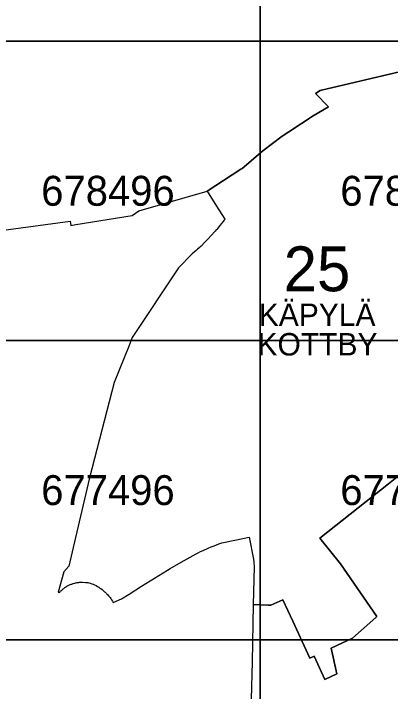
# Model space of a CAD drawing. Extents: x 25485000 to 25520000, y 6656775 to 6690000.
# Drawn here: x 25496176 to 25497436, y 6676827 to 6679092 of the extents above; entities that cross this region are included whole.
import ezdxf

# ---------------------------------------------------------------- set-up
doc = ezdxf.new("R2010")
doc.units = 0
doc.layers.add('Level 63', color=7, linetype='Continuous')

msp = doc.modelspace()

# ---------------------------------------------------------------- linework, layer by layer
at = {"layer": 'Level 63'}
for points in [[(25496000, 6679000), (25497000, 6679000), (25497000, 6680000), (25496000, 6680000)], [(25497000, 6679000), (25498000, 6679000), (25498000, 6680000), (25497000, 6680000)], [(25496000, 6678000), (25497000, 6678000), (25497000, 6679000), (25496000, 6679000)], [(25497000, 6678000), (25498000, 6678000), (25498000, 6679000), (25497000, 6679000)], [(25496000, 6677000), (25497000, 6677000), (25497000, 6678000), (25496000, 6678000)], [(25497000, 6677000), (25498000, 6677000), (25498000, 6678000), (25497000, 6678000)], [(25496000, 6676000), (25497000, 6676000), (25497000, 6677000), (25496000, 6677000)], [(25497000, 6676000), (25498000, 6676000), (25498000, 6677000), (25497000, 6677000)]]:
    msp.add_lwpolyline(points, close=True, dxfattribs=at)
for points in [[(25495688, 6678307.4), (25496365.4, 6678399), (25496367.4, 6678384.1), (25496384.4, 6678386.9), (25496572.1, 6678417.8), (25496594.5, 6678432.7), (25496823.4, 6678498.8), (25496936.3, 6678571.8), (25496939.8, 6678574.8), (25497009.6, 6678633.8), (25497074.2, 6678682.5), (25497096, 6678696.7), (25497178, 6678750.3), (25497228.6, 6678780), (25497185.7, 6678824.9), (25497201, 6678835), (25497812.2, 6678979.1)], [(25497812.2, 6678979.1), (25497201, 6678835), (25497185.7, 6678824.9), (25497228.6, 6678780), (25497178, 6678750.3), (25497096, 6678696.7), (25497074.2, 6678682.5), (25497009.6, 6678633.8), (25496939.8, 6678574.8), (25496936.3, 6678571.8), (25496823.4, 6678498.8), (25496854.6, 6678448.8), (25496882, 6678404.7), (25496880.8, 6678403.2), (25496879.9, 6678402), (25496874.6, 6678395.1), (25496870.8, 6678390.2), (25496865.9, 6678384), (25496861.3, 6678378.4), (25496858.5, 6678374.9), (25496855.1, 6678370.8), (25496854.4, 6678370.1), (25496853.9, 6678369.5), (25496849.8, 6678364.7), (25496837.2, 6678350.6), (25496826.9, 6678339.5), (25496814.8, 6678327.2), (25496802.8, 6678315.5), (25496795, 6678308.2), (25496791.1, 6678304.6), (25496786.6, 6678300.6), (25496773.6, 6678289.2), (25496727.3, 6678242.3), (25496572.5, 6678009.5), (25496562, 6677983.4), (25496512.2, 6677859.6), (25496429.9, 6677540.7), (25496383.2, 6677341.6), (25496360.8, 6677245.7), (25496343.8, 6677226.6), (25496325.2, 6677158.8), (25496329.3, 6677157.8), (25496331.7, 6677160.5), (25496333.1, 6677161.9), (25496334.6, 6677163.4), (25496337.1, 6677165.8), (25496339.2, 6677167.8), (25496341.5, 6677169.7), (25496343.7, 6677171.5), (25496344.9, 6677172.4), (25496346.3, 6677173.5), (25496347.5, 6677174.3), (25496351.7, 6677177.1), (25496354.6, 6677178.8), (25496356.3, 6677179.9), (25496359.1, 6677181.3), (25496361.1, 6677182.3), (25496363.3, 6677183.4), (25496365.7, 6677184.5), (25496368.6, 6677185.7), (25496370.4, 6677186.3), (25496373.2, 6677187.3), (25496375.5, 6677188.1), (25496380.6, 6677189.5), (25496383.2, 6677190.1), (25496385.7, 6677190.7), (25496388.5, 6677191.2), (25496390.3, 6677191.5), (25496393.7, 6677191.9), (25496396.1, 6677192.1), (25496406.5, 6677192.5), (25496417, 6677191.9), (25496420.8, 6677191.3), (25496424, 6677190.8), (25496427.3, 6677190.1), (25496432.6, 6677188.7), (25496437.3, 6677187.2), (25496442.6, 6677185.3), (25496447.1, 6677183.3), (25496452.1, 6677180.8), (25496456.3, 6677178.4), (25496461.3, 6677175.3), (25496463.4, 6677173.8), (25496465, 6677172.6), (25496467.6, 6677170.8), (25496472, 6677167.5), (25496475.8, 6677164.4), (25496477, 6677163.4), (25496480.1, 6677160.7), (25496481.9, 6677159.1), (25496483.3, 6677157.8), (25496484.5, 6677156.6), (25496485.2, 6677155.9), (25496487, 6677154.1), (25496488.4, 6677152.6), (25496489.6, 6677151.3), (25496489.8, 6677151.2), (25496489.8, 6677151.1), (25496489.9, 6677151), (25496490.1, 6677150.8), (25496490.4, 6677150.4), (25496491, 6677149.9), (25496493.9, 6677146.6), (25496496.4, 6677143.6), (25496498.5, 6677140.9), (25496500.9, 6677137.7), (25496502.1, 6677136), (25496503.7, 6677133.7), (25496506.5, 6677129.4), (25496509.5, 6677124.6), (25496537.2, 6677137), (25496562.1, 6677152.5), (25496604.1, 6677178.7), (25496690.7, 6677232.6), (25496699.2, 6677237.9), (25496736.8, 6677259.1), (25496776.2, 6677281.3), (25496786.8, 6677287.2), (25496792.9, 6677290.3), (25496801.4, 6677294.5), (25496809.6, 6677298.4), (25496826.3, 6677305.9), (25496837, 6677310.4), (25496847, 6677314.4), (25496862.3, 6677320.1), (25496872, 6677323.4), (25496883.8, 6677325.9), (25496942.4, 6677338.5), (25496963.3, 6677343), (25496978.2, 6677269.7), (25496979.7, 6677259.1), (25496980.5, 6677243.8), (25496977.6, 6677117.4), (25497027.6, 6677116), (25497035.9, 6677115.7), (25497076, 6677133.9), (25497109.7, 6677061.7), (25497167, 6676939.1), (25497180.6, 6676945.5), (25497217, 6676867.5), (25497257.3, 6676886.4), (25497237.6, 6676972.1), (25497308.8, 6677005.4), (25497386.8, 6677074.3), (25497390.4, 6677077.4), (25497268.9, 6677253.4), (25497200.3, 6677339.8), (25497429.3, 6677520.9), (25497468.6, 6677551.9)], [(25495688, 6678307.4), (25496365.4, 6678399), (25496367.4, 6678384.1), (25496384.4, 6678386.9), (25496572.1, 6678417.8), (25496594.5, 6678432.7), (25496823.4, 6678498.8), (25496854.6, 6678448.8), (25496882, 6678404.7), (25496880.8, 6678403.2), (25496879.9, 6678402), (25496874.6, 6678395.1), (25496870.8, 6678390.2), (25496865.9, 6678384), (25496861.3, 6678378.4), (25496858.5, 6678374.9), (25496855.1, 6678370.8), (25496854.4, 6678370.1), (25496853.9, 6678369.5), (25496849.8, 6678364.7), (25496837.2, 6678350.6), (25496826.9, 6678339.5), (25496814.8, 6678327.2), (25496802.8, 6678315.5), (25496795, 6678308.2), (25496791.1, 6678304.6), (25496786.6, 6678300.6), (25496773.6, 6678289.2), (25496727.3, 6678242.3), (25496572.5, 6678009.5), (25496562, 6677983.4), (25496512.2, 6677859.6), (25496429.9, 6677540.7), (25496383.2, 6677341.6), (25496360.8, 6677245.7), (25496343.8, 6677226.6), (25496325.2, 6677158.8), (25496329.3, 6677157.8), (25496331.7, 6677160.5), (25496333.1, 6677161.9), (25496334.6, 6677163.4), (25496337.1, 6677165.8), (25496339.2, 6677167.8), (25496341.5, 6677169.7), (25496343.7, 6677171.5), (25496344.9, 6677172.4), (25496346.3, 6677173.5), (25496347.5, 6677174.3), (25496351.7, 6677177.1), (25496354.6, 6677178.8), (25496356.3, 6677179.9), (25496359.1, 6677181.3), (25496361.1, 6677182.3), (25496363.3, 6677183.4), (25496365.7, 6677184.5), (25496368.6, 6677185.7), (25496370.4, 6677186.3), (25496373.2, 6677187.3), (25496375.5, 6677188.1), (25496380.6, 6677189.5), (25496383.2, 6677190.1), (25496385.7, 6677190.7), (25496388.5, 6677191.2), (25496390.3, 6677191.5), (25496393.7, 6677191.9), (25496396.1, 6677192.1), (25496406.5, 6677192.5), (25496417, 6677191.9), (25496420.8, 6677191.3), (25496424, 6677190.8), (25496427.3, 6677190.1), (25496432.6, 6677188.7), (25496437.3, 6677187.2), (25496442.6, 6677185.3), (25496447.1, 6677183.3), (25496452.1, 6677180.8), (25496456.3, 6677178.4), (25496461.3, 6677175.3), (25496463.4, 6677173.8), (25496465, 6677172.6), (25496467.6, 6677170.8), (25496472, 6677167.5), (25496475.8, 6677164.4), (25496477, 6677163.4), (25496480.1, 6677160.7), (25496481.9, 6677159.1), (25496483.3, 6677157.8), (25496484.5, 6677156.6), (25496485.2, 6677155.9), (25496487, 6677154.1), (25496488.4, 6677152.6), (25496489.6, 6677151.3), (25496489.8, 6677151.2), (25496489.8, 6677151.1), (25496489.9, 6677151), (25496490.1, 6677150.8), (25496490.4, 6677150.4), (25496491, 6677149.9), (25496493.9, 6677146.6), (25496496.4, 6677143.6), (25496498.5, 6677140.9), (25496500.9, 6677137.7), (25496502.1, 6677136), (25496503.7, 6677133.7), (25496506.5, 6677129.4), (25496509.5, 6677124.6), (25496537.2, 6677137), (25496562.1, 6677152.5), (25496604.1, 6677178.7), (25496690.7, 6677232.6), (25496699.2, 6677237.9), (25496736.8, 6677259.1), (25496776.2, 6677281.3), (25496786.8, 6677287.2), (25496792.9, 6677290.3), (25496801.4, 6677294.5), (25496809.6, 6677298.4), (25496826.3, 6677305.9), (25496837, 6677310.4), (25496847, 6677314.4), (25496862.3, 6677320.1), (25496872, 6677323.4), (25496883.8, 6677325.9), (25496942.4, 6677338.5), (25496963.3, 6677343), (25496978.2, 6677269.7), (25496979.7, 6677259.1), (25496980.5, 6677243.8), (25496977.6, 6677117.4), (25496973.3, 6676926.7), (25496967.4, 6676676.9)], [(25497468.6, 6677551.9), (25497429.3, 6677520.9), (25497200.3, 6677339.8), (25497268.9, 6677253.4), (25497390.4, 6677077.4), (25497386.8, 6677074.3), (25497308.8, 6677005.4), (25497237.6, 6676972.1), (25497257.3, 6676886.4), (25497217, 6676867.5), (25497180.6, 6676945.5), (25497167, 6676939.1), (25497109.7, 6677061.7), (25497076, 6677133.9), (25497035.9, 6677115.7), (25497027.6, 6677116), (25496977.6, 6677117.4), (25496973.3, 6676926.7), (25496967.4, 6676676.9)]]:
    msp.add_lwpolyline(points, dxfattribs=at)

# ---------------------------------------------------------------- texts
for s, height, p in [('678496', 100, (25496268.5, 6678450)), ('678497', 100, (25497268.5, 6678450)), ('25', 150, (25497079, 6678164.3)), ('KÄPYLÄ', 75, (25496995.9, 6678048.4)), ('KOTTBY', 75, (25496991.6, 6677949.8)), ('677496', 100, (25496268.5, 6677450)), ('677497', 100, (25497268.5, 6677450))]:
    msp.add_text(s, height=height, dxfattribs=at).set_placement(p)

doc.saveas('drawing.dxf')
